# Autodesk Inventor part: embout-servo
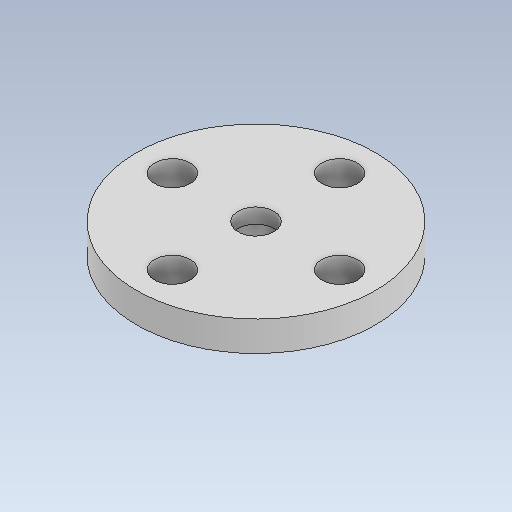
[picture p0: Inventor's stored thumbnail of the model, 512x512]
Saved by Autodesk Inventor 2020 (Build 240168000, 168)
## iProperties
Created: 2021-10
Part Number: embout-servo
Material: Générique
Document SubType Name: Modeling
Designer: bruno
Density: 1 g/cm^3
Appearance: Par défaut
Mass: 0.757985 g
Surface Area: 9.31691 cm^2
Volume: 0.757985 cm^3
Author: bruno
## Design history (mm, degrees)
sketch "Esquisse1"
  geometry: L1 (0, 0)-(2.5, 0); L2 (2, -4)-(0.5, -4); L3 (0, -3.5)-(0, -2.5); L4 (2.5, 0)-(5, 0); L5 (5, -1.5)-(5, -10); L6 (5, -10)-(2.5, -10); L7 (2.5, -10)-(2.5, -4.5); L8 (3.75, 0)-(0, 0); L9 (0, -1.5)-(0, -2.5); L10 (0, -2.5)-(3.75, -2.5); L11 (3.75, -2.5)-(3.75, -1.5); L12 (3.75, 0)-(5, 0); L13 (5, -1.5)-(3.75, -1.5); A1 r 0.5 centre (0.5, -3.5) between (0, -3.5) and (0.5, -4); A2 r 0.5 centre (2, -4.5) between (2.5, -4.5) and (2, -4)
  constraints: 26 end point, 6 parallel, 4 horizontal, 4 point on circle, 4 tangent, 2 centre point, 2 perpendicular, 2 point on line, 1 equal radius, 1 midpoint
  dimensions: "d0" = 2.5 distance of L5.end L6.end; "d1" = 5 distance between parallel lines of L3 L5; "d2" = 10 distance between parallel lines of L4 L6; "d3" = 4 distance between parallel lines of L1 L2; "d4" = 2.5 distance between parallel lines of L1 L10; "d5" = 0.5 radius of A1; "d11" = 1.5 distance between parallel lines of L12 L13
revolve "Révolution1" sketch "Esquisse1" stored, may be unused: angle "d6" = 90 deg
sketch "Esquisse2"
  geometry: C1 r 1.5 at (0, 7); 1 further point
  constraints: 1 centre point
  dimensions: "d7" = 3 diameter of C1; "d8" = 7 distance of C1.centre point (0, 0)
extrude "Extrusion1" cut sketch "Esquisse2" distance "d9" = 10; taper "d10" = 0 deg
pattern_circular "Réseau circulaire1" dims angle "d13" = 360 deg
node "Solide1"
